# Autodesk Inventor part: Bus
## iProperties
Created: 2007-06
Part Number: Bus
Material: Steel
Document SubType Name: Modeling
Designer: Phil Trethewie
Author: Phil Trethewie
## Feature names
1. Extrusion1
